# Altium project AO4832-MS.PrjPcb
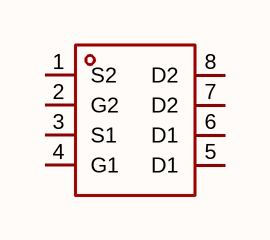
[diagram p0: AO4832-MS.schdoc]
1 sheet, 1 parts. Net scope: global (net labels, ports and power ports of the same name join across sheets).

## Sheet AO4832-MS.schdoc
size 127 x 101 mm

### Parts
Q?  ao4832-ms  [SOP-8_L4.9-W3.9-P1.27-LS6.0-BL]  (value not drawn)

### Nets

Not connected (* = marked no-connect by the designer): Q? 1(S2) 2(G2) 3(S1) 4(G1) 5(D1) 6(D1) 7(D2) 8(D2)

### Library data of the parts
Q? = ao4832-ms: 数量:2个N沟道;漏源电压(Vdss):30V;连续漏极电流(Id):10A;导通电阻(RDS(on)):10mΩ@10V;耗散功率(Pd):2W;阈值电压(Vgs(th)):1.6V;; Manufacturer: MSKSEMI(美森科); AddInBom: yes; ModelId: 75c24a7891ee4dd6bdac16a7163ff87e; ModelName: SOP-8_L4.9-W3.9-P1.27-LS6.0-BL-1; ModelTransform: 192.913,236.22,0,0,0,0,-0.393,2.749,0; Number: 2个N沟道; Drain to Source Voltage: 30V; Current - Continuous Drain(Id): 10A; Pd - Power Dissipation: 2W; Gate Threshold Voltage (Vgs(th)): 1.6V; Gate Charge(Qg): 7.4nC@4.5V; Input Capacitance(Ciss): 620pF; Reverse Transfer Capacitance (Crss@Vds): 60pF; Type: N沟道; Output Capacitance(Coss): 85pF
